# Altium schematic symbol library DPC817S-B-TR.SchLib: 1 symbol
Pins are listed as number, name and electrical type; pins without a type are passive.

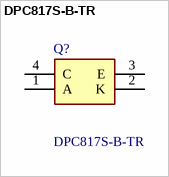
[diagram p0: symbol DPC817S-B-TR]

## DPC817S-B-TR
designator Q?
Transistor Output Optocouplers Photo Coupler SL-4 T&R 2K; Manufacturer_Name: Diodes Incorporated; Geometry.Height: 4.1mm
footprint DPC817SBTR
pins: 1 A, 2 K, 3 E, 4 C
